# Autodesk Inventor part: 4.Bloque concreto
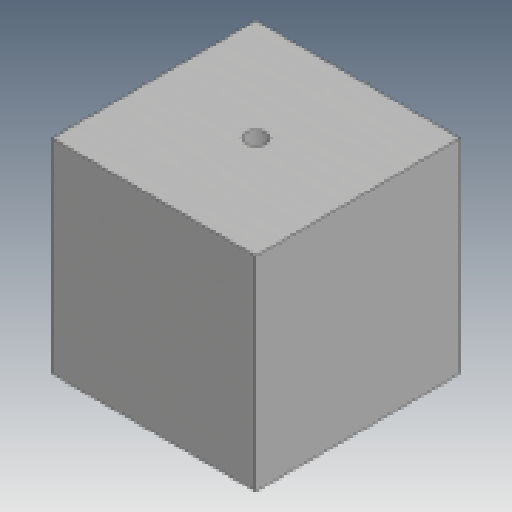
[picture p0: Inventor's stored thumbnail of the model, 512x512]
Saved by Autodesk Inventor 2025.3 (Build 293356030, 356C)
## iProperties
Created: 2025-10
Part Number: 4.Bloque concreto
Material: Genérico
Document SubType Name: Chapa
Designer: User
Density: 1 g/cm^3
Appearance: Valor por defecto
Sheet Metal Rule: Por defecto
Author: User
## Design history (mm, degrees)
sketch "Boceto1"
  geometry: L1 (-186.716, 188.346)-(13.284, 188.346); L2 (13.284, 188.346)-(13.284, -11.654); L3 (13.284, -11.654)-(-186.716, -11.654); L4 (-186.716, -11.654)-(-186.716, 188.346); 1 further point
  constraints: 8 end point, 2 parallel, 1 horizontal, 1 perpendicular
  dimensions: "d0" = 11.65406 distance from line of L3 point (0, 0); "d1" = 13.284 distance from line of L2 point (0, 0); "d2" = 200 distance of L1.end L2.end; "d3" = 200 distance of L2.end L3.end
extrude "Extrusión1" new body sketch "Boceto1" stored distance "d4" = 200; taper "d5" = 0 deg
sketch "Boceto2"
  geometry: L1 (200, 0)-(0, 0) reference; L2 (0, 200)-(0, 0) reference; 3 further points
  constraints: 1 midpoint
  dimensions: "d6" = 100 distance from line of L1 point (100, 100); "d7" = 100 distance of point (0, 100) point (100, 100)
hole "Agujero1" sketch "Boceto2" at (100, 100) diameter "d8" = 20; stored, may be unused: countersink angle "d12" = 90 deg, drill point angle "d14" = 0 deg; dims "d9" = 24, "d10" = 4, "d11" = 2, "d13" = 150
node "Sólido1"
node "Acabados"
node "Finish1" dims "Finish1_Area" = 24942.4778
other parameters: "Grosor" = 3.048 (derived), "FactorK" = 4.4, "Radio_pliegue" = 3.048 (= Grosor), "Anchura_desahogo_plegado" = 3.048 (= Grosor), "Profundidad_desahogo_plegado" = 1.524 (= 0.5 x Grosor), "Tamaño_destalonado" = 12.192 (= 4 x Grosor), "Separación_entre_unión" = 0.01, "Remanente_mínimo" = 6.096 (= 2 x Grosor), "Radiodetransición" = 3.048 (= Radio_pliegue), "Tamaño_de_radio_de_Jacobi" = 3.048 (= Radio_pliegue), "TamañoSeparación" = 3.048 (= Grosor)
